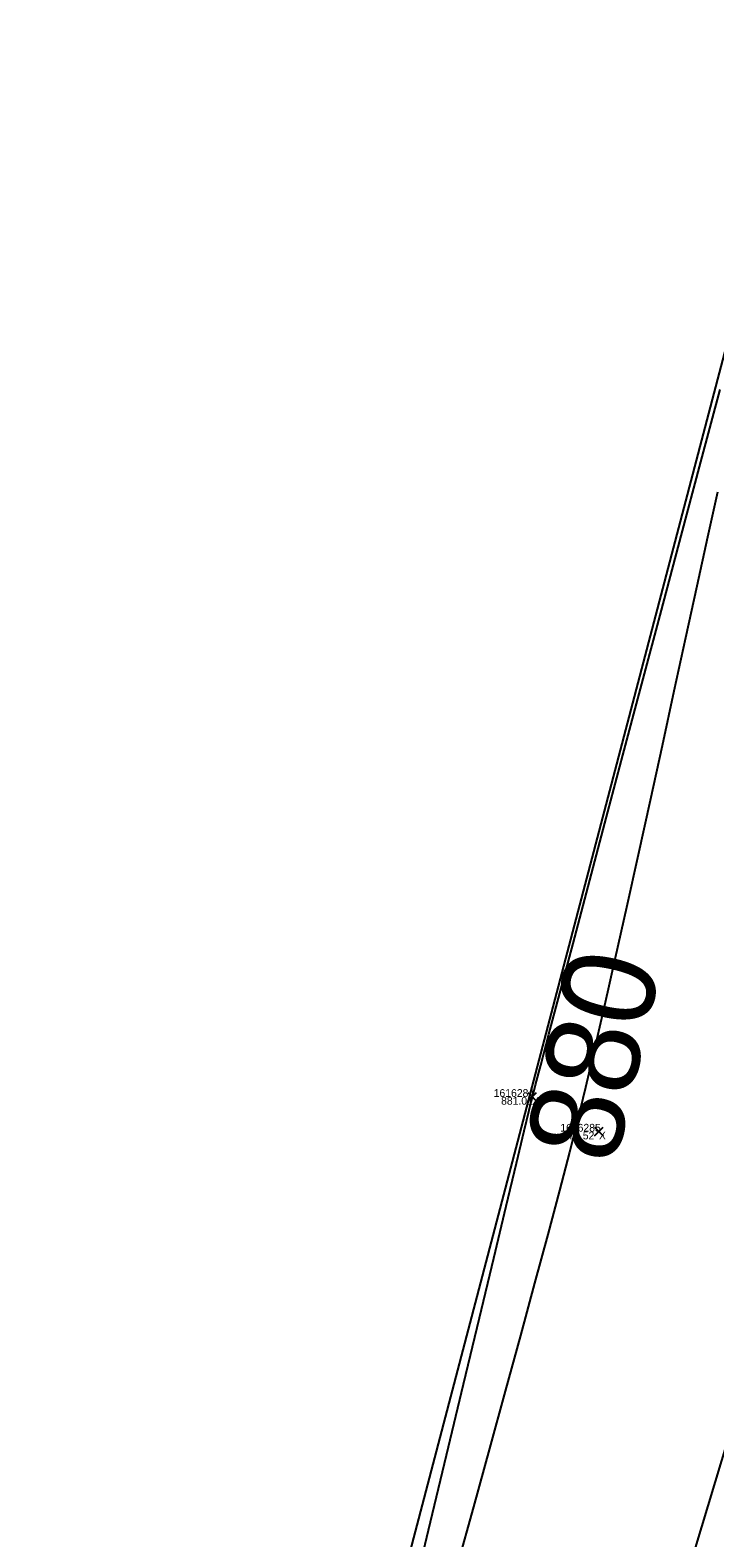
# Model space of a CAD drawing. Extents: x 1957117 to 1971063, y 701601 to 715861.
# Drawn here: x 1963309.6 to 1963340.5, y 706273.8 to 706341.7 of the extents above; entities that cross this region are included whole.
import ezdxf

# ---------------------------------------------------------------- set-up
doc = ezdxf.new("R2010")
doc.units = 0
for name, color, linetype in [('AP_X_Lights', 7, 'Continuous'), ('DT_X_Break_Line', 7, 'Continuous'), ('DT_X_Contour_Major', 7, 'Continuous'), ('DT_X_Contour_Minor', 7, 'Continuous'), ('DT_X_TIN_Hull', 7, 'Continuous'), ('HY_X_Water_Edge', 7, 'Continuous'), ('PV_P_Shoulder', 7, 'Continuous'), ('RS_Raster1', 7, 'Continuous'), ('SC_Scratch1', 7, 'Continuous'), ('SC_Shading5', 7, 'Continuous')]:
    doc.layers.add(name, color=color, linetype=linetype)

msp = doc.modelspace()

# ---------------------------------------------------------------- linework, layer by layer
at = {"layer": 'AP_X_Lights'}
for p, q in [((1963332.031, 706293.458), (1963332.419, 706293.848)), ((1963332.031, 706293.848), (1963332.419, 706293.458)), ((1963335.036, 706291.893), (1963335.424, 706292.283)), ((1963335.036, 706292.283), (1963335.424, 706291.893))]:
    msp.add_line(p, q, dxfattribs=at)
at = {"layer": 'DT_X_Break_Line'}
msp.add_lwpolyline([(1963218.329, 705756.178), (1963229.265, 705808.356), (1963234.8, 705853.147), (1963240.079, 705903.468), (1963258.033, 705954.684), (1963270.287, 705999.321), (1963276.323, 706049.345), (1963291.502, 706096.678), (1963290.138, 706117.655), (1963319.921, 706191.295), (1963330.374, 706242.631), (1963344.413, 706289.409), (1963345.772, 706340.009), (1963383.117, 706434.704), (1963392.11, 706487.426), (1963408.164, 706535.687), (1963423.633, 706582.721), (1963435.242, 706630.63), (1963443.084, 706680.696), (1963464.732, 706726.815), (1963480.654, 706774.214), (1963508.465, 706799.669), (1963511.002, 706809.48)], dxfattribs=at)
at = {"layer": 'DT_X_Contour_Major'}
msp.add_lwpolyline([(1963340.575, 706320.921), (1963340.126, 706318.881), (1963339.645, 706316.68), (1963339.138, 706314.355), (1963338.612, 706311.944), (1963338.075, 706309.484), (1963337.534, 706307.014), (1963336.997, 706304.571), (1963336.471, 706302.193), (1963335.963, 706299.917), (1963335.481, 706297.781), (1963335.032, 706295.824), (1963334.623, 706294.081), (1963334.263, 706292.592), (1963333.9, 706291.157), (1963333.449, 706289.429), (1963332.923, 706287.448), (1963332.334, 706285.255), (1963331.693, 706282.891), (1963331.012, 706280.395), (1963330.303, 706277.808), (1963329.577, 706275.171), (1963328.847, 706272.524)], dxfattribs=at)
msp.add_lwpolyline([(1963340.575, 706320.921), (1963340.126, 706318.881), (1963339.645, 706316.68), (1963339.138, 706314.355), (1963338.612, 706311.944), (1963338.075, 706309.484), (1963337.534, 706307.014), (1963336.997, 706304.571), (1963336.471, 706302.193), (1963335.963, 706299.917), (1963335.481, 706297.781), (1963335.032, 706295.824), (1963334.623, 706294.081), (1963334.263, 706292.592), (1963333.9, 706291.157), (1963333.449, 706289.429), (1963332.923, 706287.448), (1963332.334, 706285.255), (1963331.693, 706282.891), (1963331.012, 706280.395), (1963330.303, 706277.808), (1963329.577, 706275.171), (1963328.847, 706272.524)], dxfattribs=at)
at = {"layer": 'DT_X_Contour_Minor'}
msp.add_lwpolyline([(1963326.724, 706270.645), (1963327.554, 706274.124), (1963328.361, 706277.498), (1963329.129, 706280.707), (1963329.843, 706283.689), (1963330.488, 706286.384), (1963331.05, 706288.728), (1963331.514, 706290.662), (1963331.865, 706292.124), (1963332.088, 706293.051), (1963332.168, 706293.384), (1963332.206, 706293.522), (1963332.239, 706293.646), (1963332.266, 706293.764), (1963332.292, 706293.883), (1963332.376, 706294.199), (1963332.611, 706295.085), (1963332.981, 706296.481), (1963333.471, 706298.329), (1963334.065, 706300.569), (1963334.748, 706303.143), (1963335.503, 706305.991), (1963336.316, 706309.055), (1963337.17, 706312.275), (1963338.05, 706315.594), (1963338.94, 706318.951), (1963339.825, 706322.288), (1963340.689, 706325.546)], dxfattribs=at)
msp.add_lwpolyline([(1963326.724, 706270.645), (1963327.554, 706274.124), (1963328.361, 706277.498), (1963329.129, 706280.707), (1963329.843, 706283.689), (1963330.488, 706286.384), (1963331.05, 706288.728), (1963331.514, 706290.662), (1963331.865, 706292.124), (1963332.088, 706293.051), (1963332.168, 706293.384), (1963332.206, 706293.522), (1963332.239, 706293.646), (1963332.266, 706293.764), (1963332.292, 706293.883), (1963332.376, 706294.199), (1963332.611, 706295.085), (1963332.981, 706296.481), (1963333.471, 706298.329), (1963334.065, 706300.569), (1963334.748, 706303.143), (1963335.503, 706305.991), (1963336.316, 706309.055), (1963337.17, 706312.275), (1963338.05, 706315.594), (1963338.94, 706318.951), (1963339.825, 706322.288), (1963340.689, 706325.546)], dxfattribs=at)
at = {"layer": 'DT_X_TIN_Hull'}
msp.add_lwpolyline([(1963495.509, 706817.37), (1963480.654, 706774.214), (1963464.732, 706726.815), (1963443.084, 706680.696), (1963439.989, 706681.954), (1963422.341, 706634.767), (1963409.759, 706587.541), (1963383.299, 706489.662), (1963371.06, 706438.048), (1963369.543, 706438.68), (1963344.28, 706340.158), (1963318.949, 706243.571), (1963307.297, 706195.415), (1963288.342, 706117.136), (1963272.445, 706050.395), (1963261.075, 706002.095), (1963254.734, 705951.873), (1963238.207, 705904.757)], dxfattribs=at)
at = {"layer": 'HY_X_Water_Edge'}
msp.add_spline([(1963191.723, 701994.048), (1963062.047, 702441.167), (1962863.491, 703169.356), (1962827.53, 703438.691), (1962823.213, 703537.412), (1962817.962, 703593.874), (1962817.97, 703697.316), (1962828.582, 703804.235), (1962836.461, 703844.734), (1962850.687, 703896.004), (1962867.251, 703938.846), (1962873.848, 703992.355), (1962884.135, 704091.371), (1962891.241, 704140.854), (1962897.382, 704180.529), (1962905.467, 704230.979), (1962943.949, 704328.022), (1962948.537, 704378.842), (1962964.114, 704426.264), (1963004.885, 704570.73), (1963042.054, 704716.522), (1963062.038, 704814.417), (1963072.171, 704860.237), (1963090.023, 704956.798), (1963107.066, 705031.783), (1963133.773, 705105.742), (1963148.685, 705206.74), (1963175.48, 705301.059), (1963191.635, 705353.417), (1963210.988, 705447.286), (1963219.532, 705497.27), (1963230.124, 705549.475), (1963251.052, 705591.159), (1963275.289, 705693.429), (1963292.982, 705784.032), (1963302.841, 705839.645), (1963335.126, 705936.766), (1963359.752, 706046.75), (1963389.133, 706177.299), (1963417.827, 706273.456), (1963475.868, 706451.902), (1963533.782, 706640.53), (1963553.86, 706696.984), (1963580.184, 706715.425), (1963609.172, 706718.73), (1963617.062, 706714.691), (1963619.447, 706694.678), (1963564.282, 706533.07), (1963531.853, 706395.229), (1963434.4, 706006.96), (1963354.09, 705679.186), (1963237.513, 705206.07), (1963167.369, 704892.962), (1963059.145, 704434.176), (1962907.914, 703908.742), (1962877.458, 703703.326), (1962898.357, 703412.121), (1962942.65, 703052.267), (1963048.963, 702674.866), (1963191.468, 702189.666), (1963245.396, 702019.832)], degree=3, dxfattribs=at)
at = {"layer": 'SC_Shading5'}
for points in [[(1963026.912, 704294.121), (1963138.818, 704737.794), (1963251.679, 705213.963), (1963374.306, 705730.111), (1963454.783, 706045.593), (1963517.244, 706296.713), (1963562.763, 706479.256), (1963580.13, 706553.799), (1963589.678, 706586.994)], [(1963609.915, 706579.703), (1963587.283, 706499.153), (1963552.056, 706354.005), (1963480.911, 706069.234), (1963357.401, 705576.869), (1963272.751, 705226.931), (1963210.247, 704956.481), (1963044.97, 704288.881)]]:
    msp.add_spline(points, degree=3, dxfattribs=at)

# ---------------------------------------------------------------- texts
at = {"layer": 'DT_X_Contour_Major'}
msp.add_text('880', height=4.2, rotation=77.08452, dxfattribs=at).set_placement((1963335.964, 706290.495))
at = {"layer": 'PV_P_Shoulder'}
for s, p in [('881.01', (1963330.822, 706293.303)), ('879.52', (1963333.593, 706291.738))]:
    msp.add_text(s, height=0.35, dxfattribs=at).set_placement(p)
at = {"layer": 'RS_Raster1'}
for s, p in [('1616284', (1963330.489, 706293.653)), ('1616285', (1963333.491, 706292.088))]:
    msp.add_text(s, height=0.35, dxfattribs=at).set_placement(p)
at = {"layer": 'SC_Scratch1'}
for p in [(1963332.225, 706293.303), (1963335.23, 706291.738)]:
    msp.add_text('X', height=0.35, dxfattribs=at).set_placement(p)

doc.saveas('drawing.dxf')
